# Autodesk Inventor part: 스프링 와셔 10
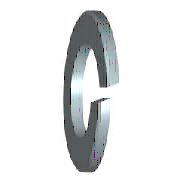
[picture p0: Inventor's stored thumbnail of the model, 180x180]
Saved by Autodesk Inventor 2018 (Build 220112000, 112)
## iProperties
Created: 2012-02
Part Number: 스프링 와셔 10
Material: 강철, 연강
Description: 스프링 잠금 와셔
Document SubType Name: Modeling
Standard: KS B 1324
Designer: mduedu
Standards Organization: KS
Language: ko-KR
Size Designation: 번호 2 - 10
Categories: <MemberInstance><Categories><Category DisplayName="조임쇠" InternalName="e4da775c-781d-43d5-af7c-5136215cf5a6" Mnemonic="FSTN"><Category DisplayName="와셔" InternalN
Density: 1 g/cm^3
Appearance: 강철
IsCustomPart: 1
Author: mduedu
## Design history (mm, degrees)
sketch "스케치1"
  geometry: C1 r 8.8 at (0, 0); C2 r 5.1 at (0, 0); 1 further point
  constraints: 2 centre point, 2 coincident
  dimensions: "d0" = 10.2 diameter of C2 (= SD1); "d1" = 17.6 diameter of C1 (= SD2)
extrude "본체" new body sketch "스케치1" distance "d2" = 2.5 (= SD); taper "d3" = 0 deg
sketch "스케치2"
  geometry: L1 (0, -5.1)-(0, 5.1) reference; L2 (2.5, 8.8)-(2.5, -8.8) reference; L3 (-1.2, 0)-(7.2, 0) reference; L4 (0, -0.5)-(2.5, 0.41); L5 (0, 0.5)-(2.5, 1.41)
  constraints: 4 end point, 4 point on line, 1 parallel
  dimensions: "d4" = 0.5 distance from line of L3 L4.start (= 0.2 x SD); "d5" = 0.5 distance from line of L3 L5.start (= 0.2 x SD); "d6" = 70 deg angle of L2 L4 (= FAWI)
extrude "절단부" cut sketch "스케치2" stored distance "d7" = 2.5 (= SD); taper "d8" = 0 deg
workaxis "Work Axis1"
workplane "Work Plane1"
body "Solid1"
other parameters: "SD1" = 10.2 [user parameter; used in 1 equation term], "SD2" = 17.6 [user parameter; used in 1 equation term], "SD" = 2.5 [user parameter; used in 4 equation terms], "FAWI" = 70 deg [user parameter; used in 1 equation term], "d9" = 0, "d10" = 0, "d11" = 0, "d12" = 0, "SDI" = 3.7 [user parameter]
